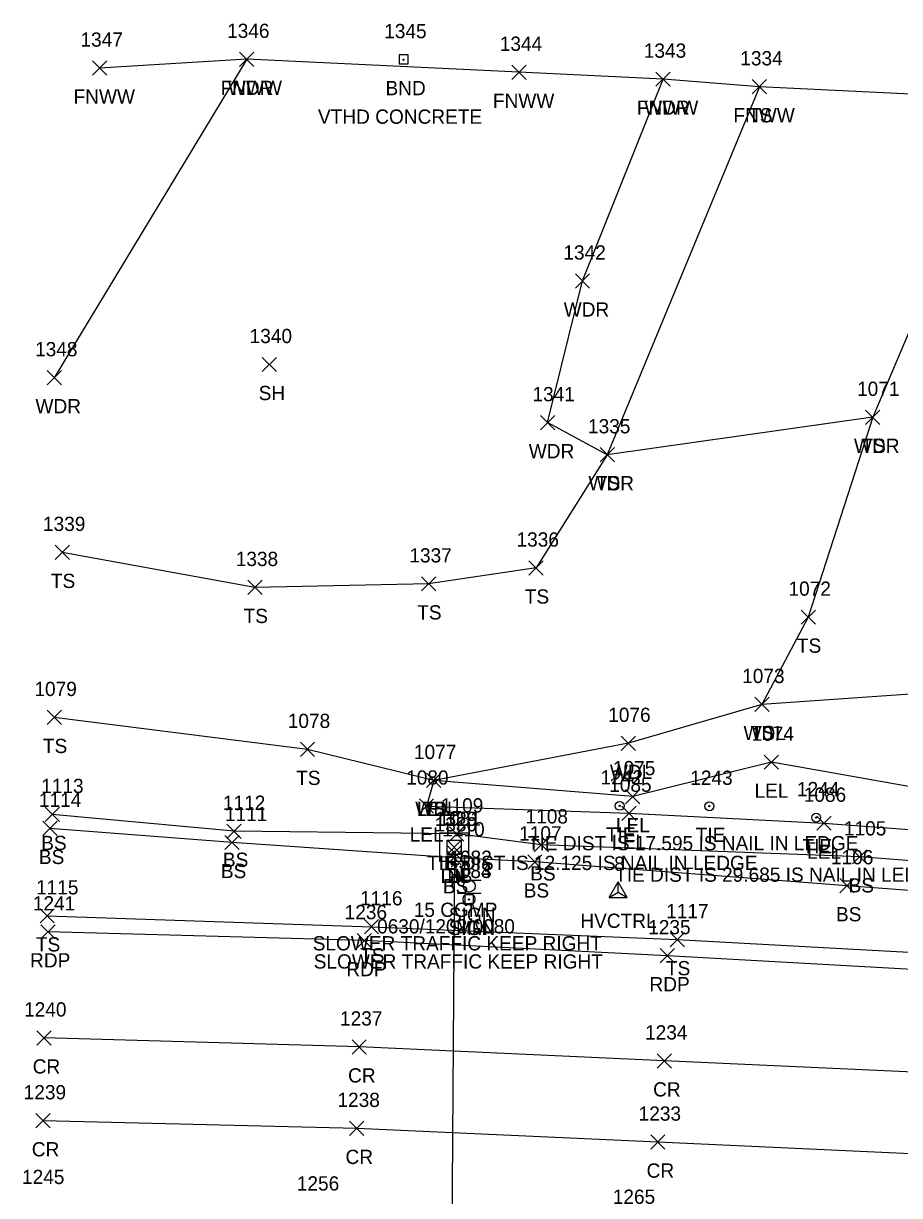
# Model space of a CAD drawing. Extents: x 1629176 to 1637209, y 606063 to 610167.
# Drawn here: x 1629179.5 to 1629302.4, y 607056.5 to 607220.9 of the extents above; entities that cross this region are included whole.
import ezdxf

# ---------------------------------------------------------------- set-up
doc = ezdxf.new("R2010")
doc.units = 0
for name, color, linetype in [('C_A', 7, 'Continuous'), ('C_C', 7, 'Continuous'), ('C_I', 7, 'Continuous'), ('CBP', 7, 'Continuous'), ('CPSM', 7, 'Continuous'), ('D_A', 7, 'Continuous'), ('D_C', 7, 'Continuous'), ('D_I', 7, 'Continuous'), ('D_TIC', 7, 'Continuous'), ('DCP', 7, 'Continuous'), ('DS', 7, 'Continuous'), ('L_A', 7, 'Continuous'), ('L_I', 7, 'Continuous'), ('L_TIC', 7, 'Continuous'), ('LARO', 7, 'Continuous'), ('LAWA', 7, 'Continuous'), ('LELB', 7, 'Continuous'), ('LFNC', 7, 'Continuous'), ('M_A', 7, 'Continuous'), ('M_C', 7, 'Continuous'), ('M_I', 7, 'Continuous'), ('MHBP', 7, 'Continuous'), ('P_A', 7, 'Continuous'), ('P_I', 7, 'Continuous'), ('P_TIC', 7, 'Continuous'), ('PET', 7, 'Continuous'), ('PRC', 7, 'Continuous'), ('S_A', 7, 'Continuous'), ('S_C', 7, 'Continuous'), ('S_I', 7, 'Continuous'), ('SRM', 7, 'Continuous'), ('SSGN', 7, 'Continuous')]:
    doc.layers.add(name, color=color, linetype=linetype)

msp = doc.modelspace()

# ---------------------------------------------------------------- linework, layer by layer
at = {"layer": 'CBP'}
for centre, radius in [((1629263.12, 607111.14), 0.625), ((1629263.12, 607111.14), 0.0833), ((1629275.71, 607111.09), 0.625), ((1629275.71, 607111.09), 0.0833), ((1629290.69, 607109.49), 0.625), ((1629290.69, 607109.49), 0.0833)]:
    msp.add_circle(centre, radius, dxfattribs=at)
at = {"layer": 'CPSM'}
for p, q in [((1629261.66, 607098.3), (1629262.91, 607100.47)), ((1629264.16, 607098.3), (1629262.91, 607100.47)), ((1629262.91, 607099.02), (1629262.91, 607100.47)), ((1629261.66, 607098.3), (1629262.91, 607099.02)), ((1629261.66, 607098.3), (1629264.16, 607098.3)), ((1629262.91, 607099.02), (1629262.91, 607099.02)), ((1629262.91, 607099.02), (1629264.16, 607098.3))]:
    msp.add_line(p, q, dxfattribs=at)
at = {"layer": 'D_TIC'}
for points in [[(1629238.9, 607104.32), (1629240.9, 607106.32)], [(1629240.9, 607104.32), (1629238.9, 607106.32)], [(1629238.94, 607103.56), (1629240.94, 607105.56)], [(1629240.94, 607103.56), (1629238.94, 607105.56)]]:
    msp.add_lwpolyline(points, dxfattribs=at)
at = {"layer": 'DCP'}
msp.add_lwpolyline([(1629239.94, 607104.56), (1629239.44, 607031.02)], dxfattribs=at)
at = {"layer": 'DS'}
for p, q in [((1629237.9, 607107.34), (1629241.9, 607107.34)), ((1629237.9, 607103.34), (1629237.9, 607107.34)), ((1629241.9, 607107.34), (1629241.9, 607103.34)), ((1629238.9, 607104.34), (1629238.9, 607106.34)), ((1629238.9, 607106.34), (1629240.9, 607106.34)), ((1629240.9, 607106.34), (1629240.9, 607104.34)), ((1629240.9, 607104.34), (1629238.9, 607104.34)), ((1629239.9, 607105.34), (1629239.9, 607105.34)), ((1629239.9, 607105.34), (1629239.9, 607105.34)), ((1629241.9, 607103.34), (1629237.9, 607103.34))]:
    msp.add_line(p, q, dxfattribs=at)
at = {"layer": 'L_TIC'}
for points in [[(1629209.8, 607214.89), (1629211.8, 607216.89)], [(1629211.8, 607214.89), (1629209.8, 607216.89)], [(1629209.8, 607214.89), (1629211.8, 607216.89)], [(1629211.8, 607214.89), (1629209.8, 607216.89)], [(1629189.17, 607213.66), (1629191.17, 607215.66)], [(1629191.17, 607213.66), (1629189.17, 607215.66)], [(1629247.99, 607213.08), (1629249.99, 607215.08)], [(1629249.99, 607213.08), (1629247.99, 607215.08)], [(1629268.2, 607212.11), (1629270.2, 607214.11)], [(1629270.2, 607212.11), (1629268.2, 607214.11)], [(1629268.2, 607212.11), (1629270.2, 607214.11)], [(1629270.2, 607212.11), (1629268.2, 607214.11)], [(1629281.73, 607211.04), (1629283.73, 607213.04)], [(1629283.73, 607211.04), (1629281.73, 607213.04)], [(1629281.73, 607211.04), (1629283.73, 607213.04)], [(1629283.73, 607211.04), (1629281.73, 607213.04)], [(1629256.91, 607183.79), (1629258.91, 607185.79)], [(1629258.91, 607183.79), (1629256.91, 607185.79)], [(1629212.99, 607172.07), (1629214.99, 607174.07)], [(1629214.99, 607172.07), (1629212.99, 607174.07)], [(1629182.81, 607170.22), (1629184.81, 607172.22)], [(1629184.81, 607170.22), (1629182.81, 607172.22)], [(1629297.62, 607164.66), (1629299.62, 607166.66)], [(1629299.62, 607164.66), (1629297.62, 607166.66)], [(1629297.62, 607164.66), (1629299.62, 607166.66)], [(1629299.62, 607164.66), (1629297.62, 607166.66)], [(1629252.01, 607163.91), (1629254.01, 607165.91)], [(1629254.01, 607163.91), (1629252.01, 607165.91)], [(1629260.38, 607159.41), (1629262.38, 607161.41)], [(1629262.38, 607159.41), (1629260.38, 607161.41)], [(1629260.38, 607159.41), (1629262.38, 607161.41)], [(1629262.38, 607159.41), (1629260.38, 607161.41)], [(1629183.92, 607145.71), (1629185.92, 607147.71)], [(1629185.92, 607145.71), (1629183.92, 607147.71)], [(1629250.4, 607143.52), (1629252.4, 607145.52)], [(1629252.4, 607143.52), (1629250.4, 607145.52)], [(1629210.95, 607140.79), (1629212.95, 607142.79)], [(1629212.95, 607140.79), (1629210.95, 607142.79)], [(1629235.31, 607141.29), (1629237.31, 607143.29)], [(1629237.31, 607141.29), (1629235.31, 607143.29)], [(1629288.57, 607136.62), (1629290.57, 607138.62)], [(1629290.57, 607136.62), (1629288.57, 607138.62)], [(1629282.07, 607124.37), (1629284.07, 607126.37)], [(1629284.07, 607124.37), (1629282.07, 607126.37)], [(1629282.07, 607124.37), (1629284.07, 607126.37)], [(1629284.07, 607124.37), (1629282.07, 607126.37)], [(1629182.8, 607122.55), (1629184.8, 607124.55)], [(1629184.8, 607122.55), (1629182.8, 607124.55)], [(1629263.34, 607118.92), (1629265.34, 607120.92)], [(1629265.34, 607118.92), (1629263.34, 607120.92)], [(1629218.33, 607118.07), (1629220.33, 607120.07)], [(1629220.33, 607118.07), (1629218.33, 607120.07)], [(1629283.4, 607116.27), (1629285.4, 607118.27)], [(1629285.4, 607116.27), (1629283.4, 607118.27)], [(1629236.03, 607113.71), (1629238.03, 607115.71)], [(1629238.03, 607113.71), (1629236.03, 607115.71)], [(1629236.03, 607113.71), (1629238.03, 607115.71)], [(1629238.03, 607113.71), (1629236.03, 607115.71)], [(1629236.03, 607113.71), (1629238.03, 607115.71)], [(1629238.03, 607113.71), (1629236.03, 607115.71)], [(1629263.96, 607111.44), (1629265.96, 607113.44)], [(1629265.96, 607111.44), (1629263.96, 607113.44)], [(1629182.53, 607108.94), (1629184.53, 607110.94)], [(1629184.53, 607108.94), (1629182.53, 607110.94)], [(1629235.02, 607110.12), (1629237.02, 607112.12)], [(1629237.02, 607110.12), (1629235.02, 607112.12)], [(1629263.43, 607109.11), (1629265.43, 607111.11)], [(1629265.43, 607109.11), (1629263.43, 607111.11)], [(1629182.2, 607106.98), (1629184.2, 607108.98)], [(1629184.2, 607106.98), (1629182.2, 607108.98)], [(1629290.77, 607107.71), (1629292.77, 607109.71)], [(1629292.77, 607107.71), (1629290.77, 607109.71)], [(1629208.02, 607106.58), (1629210.02, 607108.58)], [(1629210.02, 607106.58), (1629208.02, 607108.58)], [(1629239.26, 607106.21), (1629241.26, 607108.21)], [(1629241.26, 607106.21), (1629239.26, 607108.21)], [(1629207.74, 607105), (1629209.74, 607107)], [(1629209.74, 607105), (1629207.74, 607107)], [(1629251.13, 607104.67), (1629253.13, 607106.67)], [(1629253.13, 607104.67), (1629251.13, 607106.67)], [(1629238.88, 607102.86), (1629240.88, 607104.86)], [(1629240.88, 607102.86), (1629238.88, 607104.86)], [(1629250.22, 607102.28), (1629252.22, 607104.28)], [(1629252.22, 607102.28), (1629250.22, 607104.28)], [(1629295.79, 607102.99), (1629297.79, 607104.99)], [(1629297.79, 607102.99), (1629295.79, 607104.99)], [(1629294.02, 607098.94), (1629296.02, 607100.94)], [(1629296.02, 607098.94), (1629294.02, 607100.94)], [(1629181.81, 607094.71), (1629183.81, 607096.71)], [(1629183.81, 607094.71), (1629181.81, 607096.71)], [(1629227.31, 607093.18), (1629229.31, 607095.18)], [(1629229.31, 607093.18), (1629227.31, 607095.18)], [(1629270.2, 607091.37), (1629272.2, 607093.37)], [(1629272.2, 607091.37), (1629270.2, 607093.37)]]:
    msp.add_lwpolyline(points, dxfattribs=at)
at = {"layer": 'LARO'}
msp.add_lwpolyline([(1629525.56, 607097.75), (1629515.16, 607097.62), (1629496.01, 607097.55), (1629454.84, 607100.2), (1629419.24, 607105.4), (1629419.23, 607105.4), (1629378.86, 607107.73), (1629367.09, 607104.98), (1629352.35, 607107.03), (1629331.53, 607114.27), (1629312.1, 607112.36), (1629284.4, 607117.27), (1629264.96, 607112.44), (1629237.03, 607114.71), (1629236.02, 607111.12), (1629264.43, 607110.11), (1629291.77, 607108.71), (1629324.64, 607106.29), (1629358.13, 607102.7), (1629389.76, 607099.17), (1629430.17, 607097.09), (1629468.65, 607094.42), (1629506.63, 607093.09)], dxfattribs=at)
at = {"layer": 'LAWA'}
for points in [[(1629210.8, 607215.89), (1629183.81, 607171.22)], [(1629316.51, 607210.37), (1629307.16, 607185.73), (1629298.62, 607165.66), (1629261.38, 607160.41), (1629253.01, 607164.91), (1629257.91, 607184.79), (1629269.2, 607213.11)], [(1629312.1, 607112.36), (1629313.32, 607127.48), (1629283.07, 607125.37), (1629264.34, 607119.92), (1629237.03, 607114.71)]]:
    msp.add_lwpolyline(points, dxfattribs=at)
at = {"layer": 'LELB'}
for points in [[(1629282.73, 607212.04), (1629261.38, 607160.41), (1629251.4, 607144.52), (1629236.31, 607142.29), (1629211.95, 607141.79), (1629184.92, 607146.71)], [(1629624.92, 607174.61), (1629622.69, 607143.68), (1629611.35, 607114.32), (1629581.53, 607116.51), (1629566.42, 607115.03), (1629550.74, 607095.26), (1629545.75, 607082.85), (1629510.01, 607084.74), (1629471.96, 607087.97), (1629425.24, 607093.21), (1629387.71, 607096.98), (1629341.68, 607100.48), (1629296.79, 607103.99), (1629252.13, 607105.67), (1629240.26, 607107.21), (1629209.02, 607107.58), (1629183.53, 607109.94)], [(1629298.62, 607165.66), (1629289.57, 607137.62), (1629283.07, 607125.37)], [(1629237.03, 607114.71), (1629219.33, 607119.07), (1629183.8, 607123.55)], [(1629683.15, 607057.43), (1629646, 607061.54), (1629600.81, 607070.68), (1629551.82, 607076.32), (1629509.64, 607081.4), (1629471.16, 607085.48), (1629425.18, 607090.24), (1629387.34, 607093.37), (1629341.71, 607096.43), (1629295.02, 607099.94), (1629251.22, 607103.28), (1629239.88, 607103.86), (1629208.74, 607106), (1629183.2, 607107.98)], [(1629182.81, 607095.71), (1629228.31, 607094.18), (1629271.2, 607092.37), (1629318.24, 607089.8), (1629361.89, 607086.6), (1629408.03, 607082.19), (1629449.64, 607077.67), (1629495.68, 607072.1), (1629543.77, 607066.01), (1629589.78, 607058.79)]]:
    msp.add_lwpolyline(points, dxfattribs=at)
at = {"layer": 'LFNC'}
msp.add_lwpolyline([(1629584.57, 607180.8), (1629561.91, 607184.66), (1629527.04, 607188.99), (1629501.6, 607191.75), (1629445.35, 607199.37), (1629407.21, 607203.61), (1629374.06, 607206.64), (1629338.82, 607209.46), (1629316.51, 607210.37), (1629282.73, 607212.04), (1629269.2, 607213.11), (1629248.99, 607214.08), (1629210.8, 607215.89), (1629190.17, 607214.66)], dxfattribs=at)
at = {"layer": 'MHBP'}
for p, q in [((1629233.43, 607216.5), (1629232.18, 607216.5)), ((1629232.18, 607216.5), (1629232.18, 607215.25)), ((1629233.43, 607216.5), (1629232.18, 607216.5)), ((1629232.18, 607216.5), (1629232.18, 607215.25)), ((1629233.43, 607215.25), (1629233.43, 607216.5)), ((1629233.43, 607215.25), (1629233.43, 607216.5)), ((1629232.18, 607215.25), (1629233.43, 607215.25)), ((1629232.18, 607215.25), (1629233.43, 607215.25))]:
    msp.add_line(p, q, dxfattribs=at)
msp.add_circle((1629232.79, 607215.84), 0.0833, dxfattribs=at)
at = {"layer": 'P_TIC'}
for points in [[(1629181.92, 607092.47), (1629183.92, 607094.47)], [(1629183.92, 607092.47), (1629181.92, 607094.47)], [(1629226.29, 607091.24), (1629228.29, 607093.24)], [(1629228.29, 607091.24), (1629226.29, 607093.24)], [(1629268.81, 607089.12), (1629270.81, 607091.12)], [(1629270.81, 607089.12), (1629268.81, 607091.12)], [(1629181.35, 607077.58), (1629183.35, 607079.58)], [(1629183.35, 607077.58), (1629181.35, 607079.58)], [(1629225.58, 607076.32), (1629227.58, 607078.32)], [(1629227.58, 607076.32), (1629225.58, 607078.32)], [(1629268.37, 607074.36), (1629270.37, 607076.36)], [(1629270.37, 607074.36), (1629268.37, 607076.36)], [(1629181.22, 607065.96), (1629183.22, 607067.96)], [(1629183.22, 607065.96), (1629181.22, 607067.96)], [(1629225.23, 607064.89), (1629227.23, 607066.89)], [(1629227.23, 607064.89), (1629225.23, 607066.89)], [(1629267.47, 607062.97), (1629269.47, 607064.97)], [(1629269.47, 607062.97), (1629267.47, 607064.97)]]:
    msp.add_lwpolyline(points, dxfattribs=at)
at = {"layer": 'PET'}
msp.add_lwpolyline([(1630115.59, 606918.47), (1630070.26, 606934.37), (1630047.19, 606942.61), (1630027.81, 606949.5), (1629999.64, 606958.79), (1629963.88, 606969.73), (1629916.37, 606983.66), (1629883.8, 606991.87), (1629841.7, 607003.38), (1629794.53, 607014.94), (1629751.13, 607024.85), (1629703.98, 607035.26), (1629666.74, 607043.02), (1629621.43, 607051.04), (1629588.28, 607056.93), (1629542.89, 607063.67), (1629493.94, 607070.34), (1629447.94, 607075.86), (1629406.53, 607080.22), (1629360.37, 607084.28), (1629316.73, 607087.48), (1629269.81, 607090.12), (1629227.29, 607092.24), (1629182.92, 607093.47)], dxfattribs=at)
at = {"layer": 'PRC'}
for points in [[(1630110.18, 606905.77), (1630065.36, 606921.68), (1630022.36, 606935.68), (1629994.71, 606945.36), (1629959.54, 606955.86), (1629913.54, 606969.37), (1629877.41, 606979.26), (1629837.69, 606989.99), (1629791.63, 607000.82), (1629746.42, 607011.44), (1629699.59, 607021.37), (1629664.04, 607028.34), (1629619.43, 607036.79), (1629585.72, 607042.18), (1629539.96, 607049.3), (1629491.45, 607056.02), (1629445.88, 607061.28), (1629404.36, 607066.23), (1629358.89, 607069.49), (1629314.63, 607073.29), (1629269.37, 607075.36), (1629226.58, 607077.32), (1629182.35, 607078.58)], [(1630105.99, 606894.95), (1630061.18, 606910.94), (1630017.61, 606925.74), (1629991.01, 606934.32), (1629955.3, 606944.84), (1629910.77, 606959.12), (1629874.52, 606969.06), (1629834.93, 606979.4), (1629788.74, 606990.13), (1629743.3, 607000.68), (1629697.98, 607010.33), (1629662.17, 607017.56), (1629618.2, 607025.81), (1629583.59, 607031.56), (1629540.4, 607037.95), (1629489.63, 607045.02), (1629444.26, 607050.14), (1629402.79, 607054.66), (1629359.1, 607058.26), (1629313.06, 607061.88), (1629268.47, 607063.97), (1629226.23, 607065.89), (1629182.22, 607066.96)]]:
    msp.add_lwpolyline(points, dxfattribs=at)
at = {"layer": 'SRM'}
for p, q in [((1629242.63, 607098.67), (1629241.38, 607098.67)), ((1629241.38, 607098.67), (1629241.38, 607097.42)), ((1629242.63, 607098.67), (1629241.38, 607098.67)), ((1629241.38, 607098.67), (1629241.38, 607097.42)), ((1629241.38, 607097.42), (1629242.63, 607097.42)), ((1629241.38, 607097.42), (1629242.63, 607097.42)), ((1629242.63, 607097.42), (1629242.63, 607098.67)), ((1629242.63, 607097.42), (1629242.63, 607098.67))]:
    msp.add_line(p, q, dxfattribs=at)
msp.add_circle((1629241.98, 607098.01), 0.0833, dxfattribs=at)
at = {"layer": 'SSGN'}
for p, q in [((1629240.38, 607100.71), (1629243.71, 607100.71)), ((1629242.02, 607099.88), (1629242.02, 607099.88)), ((1629240.34, 607098.87), (1629243.68, 607098.87)), ((1629241.99, 607098.04), (1629241.99, 607098.04))]:
    msp.add_line(p, q, dxfattribs=at)
for centre in [(1629242.02, 607099.88), (1629241.99, 607098.04)]:
    msp.add_circle(centre, 0.833, dxfattribs=at)

# ---------------------------------------------------------------- texts
at = {"layer": 'C_A'}
for s, p in [('TIE', (1629261.2, 607106.14)), ('TIE', (1629273.79, 607106.09)), ('TIE', (1629288.77, 607104.49)), ('HVCTRL', (1629257.6, 607094.02))]:
    msp.add_text(s, height=2, dxfattribs=at).set_placement(p)
at = {"layer": 'C_C'}
for s, p in [('TIE DIST IS 17.595 IS NAIL IN LEDGE', (1629250.24, 607104.91)), ('TIE DIST IS 12.125 IS NAIL IN LEDGE', (1629236.09, 607102.14)), ('TIE DIST IS 29.685 IS NAIL IN LEDGE', (1629262.48, 607100.49))]:
    msp.add_text(s, height=2, dxfattribs=at).set_placement(p)
at = {"layer": 'C_I'}
for s, p in [('1242', (1629260.43, 607114.14)), ('1243', (1629273.02, 607114.09)), ('1244', (1629287.99, 607112.49)), ('8', (1629262.34, 607102.02))]:
    msp.add_text(s, height=2, dxfattribs=at).set_placement(p)
at = {"layer": 'D_A'}
for s, p in [('DIB', (1629238, 607100.32)), ('DI', (1629238.96, 607100.34)), ('P', (1629239.32, 607099.56))]:
    msp.add_text(s, height=2, dxfattribs=at).set_placement(p)
at = {"layer": 'D_C'}
msp.add_text('15 CGMP', height=2, dxfattribs=at).set_placement((1629234.23, 607095.56))
at = {"layer": 'D_I'}
for s, p in [('1330', (1629237.16, 607107.56)), ('1329', (1629237.2, 607108.32)), ('1081', (1629237.7, 607108.34))]:
    msp.add_text(s, height=2, dxfattribs=at).set_placement(p)
at = {"layer": 'L_A'}
for s, p in [('FNWW', (1629207.14, 607210.89)), ('WDR', (1629208.16, 607210.89)), ('FNWW', (1629186.51, 607209.66)), ('FNWW', (1629245.34, 607209.08)), ('FNWW', (1629265.54, 607208.11)), ('WDR', (1629266.56, 607208.11)), ('FNWW', (1629279.07, 607207.04)), ('TS', (1629281.14, 607207.04)), ('WDR', (1629255.27, 607179.79)), ('SH', (1629212.48, 607168.07)), ('WDR', (1629181.17, 607166.22)), ('WDR', (1629250.37, 607159.91)), ('WDR', (1629295.99, 607160.66)), ('TS', (1629297.03, 607160.66)), ('WDR', (1629258.74, 607155.41)), ('TS', (1629259.79, 607155.41)), ('TS', (1629183.33, 607141.71)), ('TS', (1629249.81, 607139.52)), ('TS', (1629210.36, 607136.79)), ('TS', (1629234.72, 607137.29)), ('TS', (1629287.98, 607132.62)), ('WDL', (1629280.49, 607120.37)), ('TS', (1629281.48, 607120.37)), ('TS', (1629182.21, 607118.55)), ('TS', (1629217.74, 607114.07)), ('WDL', (1629261.75, 607114.92)), ('LEL', (1629282.04, 607112.27)), ('WDL', (1629234.45, 607109.71)), ('LEL', (1629234.67, 607109.71)), ('TS', (1629235.44, 607109.71)), ('LEL', (1629262.59, 607107.44)), ('LEL', (1629233.66, 607106.12)), ('BS', (1629181.97, 607104.94)), ('LEL', (1629262.06, 607105.11)), ('LEL', (1629289.41, 607103.71)), ('BS', (1629181.65, 607102.98)), ('BS', (1629207.46, 607102.58)), ('BS', (1629238.7, 607102.21)), ('BS', (1629207.18, 607101)), ('BS', (1629250.57, 607100.67)), ('BS', (1629238.32, 607098.86)), ('BS', (1629295.23, 607098.99)), ('BS', (1629249.66, 607098.28)), ('BS', (1629293.46, 607094.94)), ('TS', (1629181.22, 607090.71)), ('TS', (1629226.72, 607089.18)), ('TS', (1629269.61, 607087.37))]:
    msp.add_text(s, height=2, dxfattribs=at).set_placement(p)
at = {"layer": 'L_I'}
for s, p in [('1346', (1629208.05, 607218.89)), ('1346', (1629208.05, 607218.89)), ('1347', (1629187.48, 607217.66)), ('1344', (1629246.3, 607217.08)), ('1343', (1629266.5, 607216.11)), ('1343', (1629266.5, 607216.11)), ('1334', (1629280.04, 607215.04)), ('1334', (1629280.04, 607215.04)), ('1342', (1629255.22, 607187.79)), ('1340', (1629211.21, 607176.07)), ('1348', (1629181.11, 607174.22)), ('1341', (1629250.89, 607167.91)), ('1071', (1629296.42, 607168.66)), ('1071', (1629296.42, 607168.66)), ('1335', (1629258.68, 607163.41)), ('1335', (1629258.68, 607163.41)), ('1339', (1629182.22, 607149.71)), ('1336', (1629248.65, 607147.52)), ('1338', (1629209.26, 607144.79)), ('1337', (1629233.62, 607145.29)), ('1072', (1629286.8, 607140.62)), ('1073', (1629280.3, 607128.37)), ('1073', (1629280.3, 607128.37)), ('1079', (1629181.02, 607126.55)), ('1078', (1629216.56, 607122.07)), ('1076', (1629261.51, 607122.92)), ('1074', (1629281.63, 607120.27)), ('1077', (1629234.26, 607117.71)), ('1077', (1629234.26, 607117.71)), ('1077', (1629234.26, 607117.71)), ('1075', (1629262.18, 607115.44)), ('1080', (1629233.17, 607114.12)), ('1113', (1629181.97, 607112.94)), ('1085', (1629261.65, 607113.11)), ('1114', (1629181.65, 607110.98)), ('1112', (1629207.46, 607110.58)), ('1109', (1629238.04, 607110.21)), ('1086', (1629288.94, 607111.71)), ('1111', (1629207.74, 607109)), ('1108', (1629249.92, 607108.67)), ('1105', (1629294.58, 607106.99)), ('1110', (1629238.23, 607106.86)), ('1107', (1629249.02, 607106.28)), ('1106', (1629292.76, 607102.94)), ('1115', (1629181.25, 607098.71)), ('1116', (1629226.7, 607097.18)), ('1117', (1629269.64, 607095.37))]:
    msp.add_text(s, height=2, dxfattribs=at).set_placement(p)
at = {"layer": 'M_A'}
msp.add_text('BND', height=2, dxfattribs=at).set_placement((1629230.27, 607210.85))
at = {"layer": 'M_C'}
msp.add_text('VTHD CONCRETE', height=2, dxfattribs=at).set_placement((1629220.8, 607206.85))
at = {"layer": 'M_I'}
msp.add_text('1345', height=2, dxfattribs=at).set_placement((1629230.09, 607218.85))
at = {"layer": 'P_A'}
for s, p in [('RDP', (1629180.41, 607088.47)), ('RDP', (1629224.78, 607087.24)), ('RDP', (1629267.3, 607085.12)), ('CR', (1629180.78, 607073.58)), ('CR', (1629225.02, 607072.32)), ('CR', (1629267.81, 607070.36)), ('CR', (1629180.65, 607061.96)), ('CR', (1629224.66, 607060.89)), ('CR', (1629266.9, 607058.97))]:
    msp.add_text(s, height=2, dxfattribs=at).set_placement(p)
at = {"layer": 'P_I'}
for s, p in [('1241', (1629180.8, 607096.47)), ('1236', (1629224.54, 607095.24)), ('1235', (1629267.12, 607093.12)), ('1240', (1629179.57, 607081.58)), ('1237', (1629223.89, 607080.32)), ('1234', (1629266.68, 607078.36)), ('1239', (1629179.51, 607069.96)), ('1238', (1629223.53, 607068.89)), ('1233', (1629265.78, 607066.97)), ('1245', (1629179.28, 607058.08)), ('1256', (1629217.83, 607057.17)), ('1265', (1629262.15, 607055.3))]:
    msp.add_text(s, height=2, dxfattribs=at).set_placement(p)
at = {"layer": 'S_A'}
for s, p in [('SIGN', (1629239.16, 607094.86)), ('SIGN', (1629239.13, 607093.02)), ('MM', (1629240.16, 607093.01))]:
    msp.add_text(s, height=2, dxfattribs=at).set_placement(p)
at = {"layer": 'S_C'}
for s, p in [('0630/1202/0080', (1629229.09, 607093.24)), ('SLOWER TRAFFIC KEEP RIGHT', (1629220.06, 607090.86)), ('SLOWER TRAFFIC KEEP RIGHT', (1629220.2, 607088.31))]:
    msp.add_text(s, height=2, dxfattribs=at).set_placement(p)
at = {"layer": 'S_I'}
for s, p in [('1082', (1629239.23, 607102.86)), ('1083', (1629239.2, 607101.02)), ('1084', (1629239.2, 607101.01))]:
    msp.add_text(s, height=2, dxfattribs=at).set_placement(p)

doc.saveas('drawing.dxf')
